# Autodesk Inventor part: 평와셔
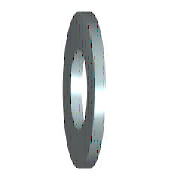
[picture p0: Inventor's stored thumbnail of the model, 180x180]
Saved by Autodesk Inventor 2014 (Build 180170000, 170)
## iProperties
IsCustomPart: 1
Created: 2012-02
Part Number: 평와셔
Material: 강철
Description: 평면 와셔 - 초대형 시리즈 - 제품 등급 C
Document SubType Name: Modeling
Standard: ISO 7094
Designer: mduedu
Standard Revision: Second edition 2000-06-01
Standards Organization: ISO
Language: ko-KR
Size Designation: ST 5 - 100 HV
Categories: <MemberInstance><Categories><Category DisplayName="조임쇠" InternalName="e4da775c-781d-43d5-af7c-5136215cf5a6" Mnemonic="FSTN"><Category DisplayName="와셔" InternalN
Density: 7.85 g/cm^3
Appearance: 강철
Author: mduedu
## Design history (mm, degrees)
sketch "스케치"
  geometry: C1 r 9 at (0, 0); C2 r 2.75 at (0, 0); 1 further point
  constraints: 2 centre point, 2 coincident
  dimensions: "d0" = 5.5 diameter of C2 (= SD1); "d1" = 18 diameter of C1 (= SD2)
extrude "본체" new body sketch "스케치" distance "d2" = 2 (= SD); taper "d3" = 0 deg
workaxis "Work Axis1"
workplane "Work Plane1"
body "Solid1"
other parameters: "SD1" = 5.5 [user parameter; used in 1 equation term], "SD2" = 18 [user parameter; used in 1 equation term], "SD" = 2 [user parameter; used in 1 equation term], "d4" = 0, "d5" = 0, "d6" = 0, "d7" = 0, "NND" = 5 [user parameter]
